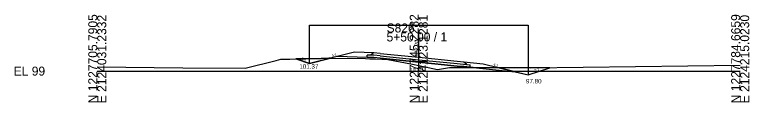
# Model space of a CAD drawing. Extents: x 2118382 to 2118616, y 1213030 to 1222057.
# Drawn here: x 2118381.9 to 2118610.4, y 1216030.1 to 1216057.3 of the extents above; entities that cross this region are included whole.
import ezdxf

# ---------------------------------------------------------------- set-up
doc = ezdxf.new("R2010")
doc.units = 0
for name, color, linetype in [('XS_CELL', 7, 'Continuous'), ('XS_M_DITCH', 7, 'Continuous'), ('XS_M_SHAPES_EARTHWORK', 7, 'Continuous'), ('XS_P_FINISHED_GRADE', 7, 'Continuous'), ('XS_P_FINISHED_GRADE_ELEV_TX', 7, 'Continuous'), ('XS_P_SUBGRADE_GRANULAR', 7, 'Continuous'), ('XS_P_SUBGRADE_PAVEMENT', 7, 'Continuous'), ('XS_P_TX_DCH', 7, 'Continuous'), ('XS_P_TX_FS_BS', 7, 'Continuous'), ('XS_X_GROUND', 7, 'Continuous'), ('XS_X_GROUND_TX', 7, 'Continuous')]:
    doc.layers.add(name, color=color, linetype=linetype)

msp = doc.modelspace()

# ---------------------------------------------------------------- linework, layer by layer
at = {"layer": 'XS_CELL'}
for p, q in [((2118507.6, 1216039.8), (2118507.6, 1216051.82)), ((2118407.6, 1216039.8), (2118507.6, 1216039.8)), ((2118507.6, 1216039.8), (2118607.6, 1216039.8))]:
    msp.add_line(p, q, dxfattribs=at)
at = {"layer": 'XS_M_DITCH'}
for p, q in [((2118473.6, 1216042.18), (2118473.6, 1216054.09)), ((2118473.6, 1216054.09), (2118541.6, 1216054.09)), ((2118541.6, 1216054.09), (2118541.6, 1216038.6))]:
    msp.add_line(p, q, dxfattribs=at)
at = {"layer": 'XS_M_SHAPES_EARTHWORK'}
for p, q in [((2118477.26, 1216043.75), (2118469.39, 1216043.58)), ((2118469.39, 1216043.58), (2118473.6, 1216042.18)), ((2118473.6, 1216042.18), (2118480.11, 1216043.8)), ((2118479.66, 1216043.81), (2118477.26, 1216043.75)), ((2118480.11, 1216043.8), (2118479.66, 1216043.81)), ((2118482.24, 1216044.33), (2118480.11, 1216043.8)), ((2118480.11, 1216043.8), (2118491, 1216043.69)), ((2118491.6, 1216044.05), (2118482.24, 1216044.33)), ((2118491, 1216043.69), (2118492.36, 1216043.67)), ((2118493.6, 1216043.99), (2118491.6, 1216044.05)), ((2118492.36, 1216043.67), (2118493.06, 1216043.65)), ((2118493.06, 1216043.65), (2118494.18, 1216043.6)), ((2118495.6, 1216043.79), (2118493.6, 1216043.99)), ((2118494.18, 1216043.6), (2118498.04, 1216043.44)), ((2118507.6, 1216042.59), (2118495.6, 1216043.79)), ((2118498.04, 1216043.44), (2118505.65, 1216041.91)), ((2118519.6, 1216041.39), (2118507.6, 1216042.59)), ((2118505.65, 1216041.91), (2118507.6, 1216041.51)), ((2118507.6, 1216041.51), (2118513.42, 1216040.33)), ((2118513.42, 1216040.33), (2118517.18, 1216040.95)), ((2118517.18, 1216040.95), (2118524.53, 1216040.9)), ((2118521.6, 1216041.19), (2118519.6, 1216041.39)), ((2118523.6, 1216040.99), (2118521.6, 1216041.19)), ((2118524.53, 1216040.9), (2118523.6, 1216040.99)), ((2118532.63, 1216040.84), (2118524.53, 1216040.9)), ((2118524.53, 1216040.9), (2118537.62, 1216039.59)), ((2118537.62, 1216039.59), (2118532.63, 1216040.84)), ((2118542.44, 1216040.77), (2118532.63, 1216040.84)), ((2118532.63, 1216040.84), (2118537.62, 1216039.59)), ((2118541.6, 1216038.6), (2118548.38, 1216040.85)), ((2118548.38, 1216040.85), (2118542.44, 1216040.77)), ((2118537.62, 1216039.59), (2118541.6, 1216038.6))]:
    msp.add_line(p, q, dxfattribs=at)
at = {"layer": 'XS_P_FINISHED_GRADE'}
for p, q in [((2118487.6, 1216045.67), (2118473.6, 1216042.18)), ((2118493.6, 1216045.49), (2118487.6, 1216045.67)), ((2118495.6, 1216045.29), (2118493.6, 1216045.49)), ((2118495.6, 1216045.29), (2118507.6, 1216044.09)), ((2118473.6, 1216042.18), (2118469.39, 1216043.58)), ((2118507.6, 1216044.09), (2118519.6, 1216042.89)), ((2118519.6, 1216042.89), (2118521.6, 1216042.69)), ((2118521.6, 1216042.69), (2118527.6, 1216042.09)), ((2118527.6, 1216042.09), (2118541.6, 1216038.6)), ((2118541.6, 1216038.6), (2118548.38, 1216040.85))]:
    msp.add_line(p, q, dxfattribs=at)
at = {"layer": 'XS_P_SUBGRADE_GRANULAR'}
for p, q in [((2118491.6, 1216044.05), (2118482.24, 1216044.33)), ((2118491.6, 1216044.05), (2118491.6, 1216044.8)), ((2118492.67, 1216044.77), (2118491.6, 1216044.8)), ((2118493.6, 1216043.99), (2118491.6, 1216044.05)), ((2118495.6, 1216043.79), (2118493.6, 1216043.99)), ((2118495.6, 1216043.79), (2118507.6, 1216042.59)), ((2118507.6, 1216042.59), (2118519.6, 1216041.39)), ((2118519.6, 1216041.39), (2118521.6, 1216041.19)), ((2118521.6, 1216041.19), (2118523.6, 1216040.99)), ((2118522.43, 1216041.86), (2118523.6, 1216041.74)), ((2118523.6, 1216040.99), (2118523.6, 1216041.74)), ((2118523.6, 1216040.99), (2118537.62, 1216039.59))]:
    msp.add_line(p, q, dxfattribs=at)
at = {"layer": 'XS_P_SUBGRADE_PAVEMENT'}
for p, q in [((2118492.87, 1216045.11), (2118492.67, 1216044.77)), ((2118493.6, 1216045.49), (2118492.87, 1216045.11)), ((2118493.6, 1216044.74), (2118492.67, 1216044.77)), ((2118495.6, 1216044.54), (2118493.6, 1216044.74)), ((2118495.6, 1216044.54), (2118507.6, 1216043.34)), ((2118507.6, 1216043.34), (2118519.6, 1216042.14)), ((2118521.6, 1216042.69), (2118522.25, 1216042.17)), ((2118519.6, 1216042.14), (2118522.43, 1216041.86)), ((2118522.25, 1216042.17), (2118522.43, 1216041.86))]:
    msp.add_line(p, q, dxfattribs=at)
at = {"layer": 'XS_X_GROUND'}
for p, q in [((2118453.61, 1216040.69), (2118463.26, 1216043.13)), ((2118463.26, 1216043.13), (2118464.69, 1216043.49)), ((2118464.69, 1216043.49), (2118465, 1216043.49)), ((2118465, 1216043.49), (2118467.48, 1216043.54)), ((2118467.48, 1216043.54), (2118477.26, 1216043.75)), ((2118477.26, 1216043.75), (2118479.66, 1216043.81)), ((2118479.66, 1216043.81), (2118491, 1216043.69)), ((2118491, 1216043.69), (2118492.36, 1216043.67)), ((2118492.36, 1216043.67), (2118493.06, 1216043.65)), ((2118493.06, 1216043.65), (2118494.18, 1216043.6)), ((2118494.18, 1216043.6), (2118498.04, 1216043.44)), ((2118498.04, 1216043.44), (2118505.65, 1216041.91)), ((2118407.6, 1216041.13), (2118434.21, 1216040.85)), ((2118434.21, 1216040.85), (2118453.61, 1216040.69)), ((2118505.65, 1216041.91), (2118507.6, 1216041.51)), ((2118507.6, 1216041.51), (2118513.42, 1216040.33)), ((2118513.42, 1216040.33), (2118517.18, 1216040.95)), ((2118517.18, 1216040.95), (2118542.44, 1216040.77)), ((2118542.44, 1216040.77), (2118575.04, 1216041.25)), ((2118575.04, 1216041.25), (2118607.6, 1216041.64))]:
    msp.add_line(p, q, dxfattribs=at)

# ---------------------------------------------------------------- texts
at = {"layer": 'XS_CELL'}
for s, p in [('N 1227705.7905', (2118407.6, 1216029.8)), ('E 2124031.2332', (2118410.4, 1216029.8)), ('N 1227745.2282', (2118507.6, 1216029.8)), ('E 2124123.1281', (2118510.4, 1216029.8)), ('N 1227784.6659', (2118607.6, 1216029.8)), ('E 2124215.0230', (2118610.4, 1216029.8))]:
    msp.add_text(s, height=2.8, rotation=90, dxfattribs=at).set_placement(p)
for s, p in [('S826', (2118497.6, 1216051.82)), ('5+50.00 / 1', (2118497.6, 1216049.02)), ('EL 99', (2118381.6, 1216038.4))]:
    msp.add_text(s, height=2.8, dxfattribs=at).set_placement(p)
at = {"layer": 'XS_P_FINISHED_GRADE_ELEV_TX'}
msp.add_text(' 103.29', height=1.25, rotation=90, dxfattribs=at).set_placement((2118507.6, 1216043.81))
at = {"layer": 'XS_P_TX_DCH'}
for s, p in [('101.37', (2118470.47, 1216040.56)), ('97.80', (2118540.97, 1216035.97))]:
    msp.add_text(s, height=1.4, dxfattribs=at).set_placement(p)
at = {"layer": 'XS_P_TX_FS_BS'}
for s, rotation, p in [('4:1', 14.0167, (2118480.65, 1216044.19)), ('3:1', 341.5651, (2118471.01, 1216043.32)), ('3:1', 341.5651, (2118471.01, 1216043.32)), ('4:1', 345.9871, (2118530.75, 1216041.52)), ('3:1', 18.4052, (2118543.75, 1216039.58))]:
    msp.add_text(s, height=0.8, rotation=rotation, dxfattribs=at).set_placement(p)
at = {"layer": 'XS_X_GROUND_TX'}
msp.add_text('100.71', height=1, dxfattribs=at).set_placement((2118504.96, 1216039.72))

doc.saveas('drawing.dxf')
